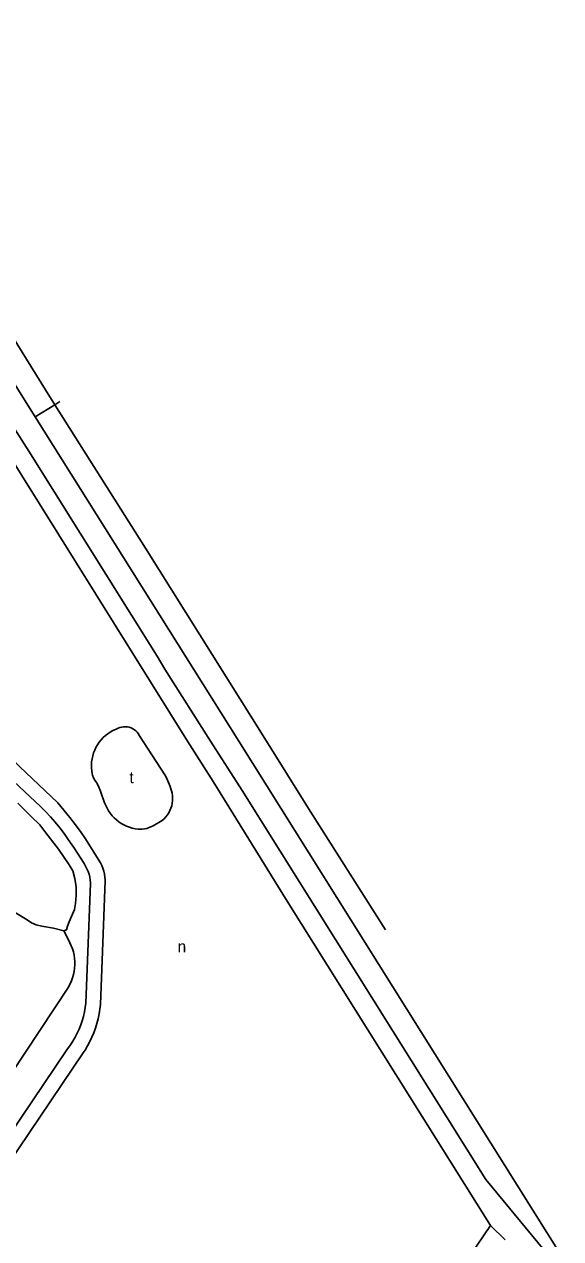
# Model space of a CAD drawing. Extents: x 158142 to 159655, y 385262 to 387204.
# Drawn here: x 159402.4 to 159588.7, y 385994 to 386415.6 of the extents above; entities that cross this region are included whole.
import ezdxf

# ---------------------------------------------------------------- set-up
doc = ezdxf.new("R2010")
doc.units = 0
for name, color, linetype in [('BLT_Basislijn', 7, 'Continuous'), ('BLT_Centroide', 7, 'Continuous'), ('BLT_Vlakafsluiter', 7, 'Continuous')]:
    doc.layers.add(name, color=color, linetype=linetype)

msp = doc.modelspace()

# ---------------------------------------------------------------- linework, layer by layer
at = {"layer": 'BLT_Basislijn'}
for p, q in [((159442.44, 386168.49), (159451.21, 386155.01)), ((159428.98, 386149.01), (159430.32, 386145.33)), ((159447.2, 386137.31), (159450.31, 386139.2)), ((159423.44, 386133.18), (159428.85, 386124.47)), ((159423.18, 386124.18), (159419.61, 386129.73)), ((159425.42, 386117.26), (159423.8, 386075.76)), ((159430.53, 386118.18), (159428.87, 386075.33)), ((159417.74, 386081.26), (159363.43, 385999.19)), ((159422.86, 386058.44), (159383.2, 386000)), ((159417.4, 386059.84), (159383.77, 386009.99)), ((159569.35, 385993.56), (159564.29, 385998.58))]:
    msp.add_line(p, q, dxfattribs=at)
for points in [[(159478.02, 386149.53), (159467.1, 386166.67), (159451.19, 386191.65), (159448.58, 386196.2), (159403.98, 386267.32), (159376.84, 386309.95), (159320.35, 386401.06), (159194.99, 386601.74), (159190.31, 386604.18), (159180.82, 386620.38), (159176.63, 386631.64), (159172.66, 386639.08), (159146.46, 386681.4), (159151.12, 386684.55)], [(159413.02, 386283.52), (159409.77, 386288.65), (159364.7, 386361.34), (159326.64, 386421.78), (159323.99, 386426.39), (159205.26, 386616.42)], [(159406.2, 386279.27), (159382.73, 386316.66), (159365.07, 386339.65), (159364.85, 386340.38), (159339.3, 386382.12), (159329.59, 386402.01), (159197.96, 386612.2)], [(159375.73, 386300.12), (159459.1, 386166.67), (159467.97, 386152.7), (159493.65, 386111.16), (159564.29, 385998.58)], [(159527.89, 386101.24), (159501.12, 386143.35), (159486.54, 386166.67), (159444.56, 386233.75), (159413.02, 386283.52)], [(159588.66, 385988.41), (159476.89, 386166.67), (159406.2, 386279.27)], [(159435, 386171.16), (159434.05, 386170.8), (159433.13, 386170.37), (159432.25, 386169.86), (159431.41, 386169.29), (159430.59, 386168.63)], [(159435, 386171.16), (159435.61, 386171.42), (159436.25, 386171.6), (159436.9, 386171.7), (159437.57, 386171.72), (159438.23, 386171.66), (159438.88, 386171.53), (159439.51, 386171.31), (159440.1, 386171.03), (159440.66, 386170.67), (159441.17, 386170.25), (159441.63, 386169.77), (159442.03, 386169.24), (159442.36, 386168.66), (159442.44, 386168.49)], [(159416.11, 386100.81), (159412.56, 386101.79), (159408.57, 386102.44), (159406.6, 386102.92), (159404.9, 386103.62), (159403.46, 386104.7), (159399.06, 386107.3), (159391.98, 386112.43), (159387.43, 386115.36), (159380.2, 386119.83), (159373.69, 386124.24), (159364.83, 386130.24), (159352.95, 386138.24), (159352.82, 386138.61), (159352.79, 386139.15), (159356.55, 386144.3), (159361.74, 386151.63), (159369, 386163.07), (159369.29, 386163.75), (159369.53, 386164.53), (159369.42, 386165.46), (159369.3, 386166.34), (159370.21, 386167.56), (159371.61, 386168.13)], [(159391.04, 386167.32), (159400.79, 386157.88), (159414.04, 386145.26)], [(159430.59, 386168.63), (159429.82, 386167.92), (159429.1, 386167.15), (159428.45, 386166.33), (159427.86, 386165.46), (159427.33, 386164.55), (159426.88, 386163.6), (159426.5, 386162.61), (159426.2, 386161.61), (159425.97, 386160.58), (159425.82, 386159.54), (159425.76, 386158.49), (159425.77, 386157.44), (159425.86, 386156.39), (159426.03, 386155.35), (159426.14, 386154.86)], [(159408.02, 386143.99), (159395.1, 386156.13), (159388.48, 386162.44)], [(159426.14, 386154.86), (159426.51, 386153.99), (159426.96, 386153.16), (159427.47, 386152.37), (159427.73, 386152.02)], [(159451.21, 386155.01), (159451.89, 386153.68), (159452.5, 386152.32), (159453.03, 386150.93), (159453.3, 386150.1)], [(159427.73, 386152.02), (159428.33, 386150.72), (159428.85, 386149.38), (159428.98, 386149.01)], [(159450.31, 386139.2), (159450.97, 386139.78), (159451.57, 386140.42), (159452.12, 386141.1), (159452.59, 386141.84), (159453, 386142.61), (159453.34, 386143.42), (159453.6, 386144.26), (159453.79, 386145.12), (159453.89, 386145.99), (159453.92, 386146.87), (159453.86, 386147.74), (159453.73, 386148.61), (159453.52, 386149.46), (159453.3, 386150.1)], [(159478.02, 386149.53), (159562.65, 386014.57), (159584.59, 385988.03), (159588.66, 385988.41)], [(159400.23, 386145.16), (159404.79, 386140.58), (159407.83, 386137.69), (159409.95, 386134.84), (159414.26, 386129.2), (159418.02, 386123.76), (159419.23, 386121.71), (159419.98, 386118.99), (159420.41, 386116.07), (159420.48, 386113.17), (159420.19, 386110.32), (159419.82, 386108.21), (159418, 386104.03), (159417.43, 386102.49), (159417.11, 386101.17), (159416.11, 386100.81)], [(159408.02, 386143.99), (159409.79, 386142.23), (159411.49, 386140.41), (159413.14, 386138.53), (159414.72, 386136.61), (159416.24, 386134.63), (159417.7, 386132.61), (159419.1, 386130.54), (159419.61, 386129.73)], [(159414.04, 386145.26), (159416.17, 386142.77), (159418.23, 386140.23), (159420.23, 386137.63), (159422.17, 386134.99), (159423.44, 386133.18)], [(159430.32, 386145.33), (159430.7, 386144.36), (159431.15, 386143.42), (159431.67, 386142.51), (159432.26, 386141.65), (159432.91, 386140.83), (159433.63, 386140.07), (159434.4, 386139.36), (159435.22, 386138.72), (159436.09, 386138.14), (159437, 386137.62), (159437.95, 386137.18), (159438.93, 386136.82), (159439.93, 386136.52), (159440.96, 386136.31), (159441.99, 386136.17), (159442.44, 386136.14)], [(159442.44, 386136.14), (159443.3, 386136.16), (159444.16, 386136.26), (159445.01, 386136.43), (159445.83, 386136.69), (159446.63, 386137.02), (159447.2, 386137.31)], [(159423.18, 386124.18), (159423.72, 386123.31), (159424.19, 386122.41), (159424.59, 386121.47), (159424.91, 386120.5), (159425.15, 386119.51), (159425.32, 386118.5), (159425.41, 386117.48), (159425.42, 386117.26)], [(159428.85, 386124.47), (159429.32, 386123.53), (159429.71, 386122.56), (159430.03, 386121.56), (159430.27, 386120.54), (159430.44, 386119.51), (159430.52, 386118.47), (159430.53, 386118.18)], [(159416.11, 386100.81), (159417.74, 386097.72), (159418.28, 386096.72), (159418.75, 386095.68), (159419.15, 386094.61), (159419.47, 386093.52), (159419.72, 386092.41), (159419.88, 386091.29), (159419.97, 386090.15), (159419.98, 386089.01), (159419.9, 386087.88), (159419.75, 386086.75), (159419.52, 386085.63), (159419.21, 386084.54), (159418.82, 386083.47), (159418.36, 386082.43), (159417.83, 386081.42), (159417.74, 386081.26)], [(159423.8, 386075.76), (159423.61, 386074.21), (159423.34, 386072.67), (159422.99, 386071.15), (159422.57, 386069.65), (159422.07, 386068.17), (159421.49, 386066.72), (159420.84, 386065.3), (159420.12, 386063.91), (159419.33, 386062.57), (159418.46, 386061.27), (159417.54, 386060.01), (159417.4, 386059.84)], [(159428.87, 386075.33), (159428.68, 386073.65), (159428.41, 386071.98), (159428.07, 386070.33), (159427.64, 386068.69), (159427.14, 386067.08), (159426.57, 386065.49), (159425.92, 386063.94), (159425.19, 386062.41), (159424.4, 386060.92), (159423.54, 386059.47), (159422.86, 386058.44)], [(159564.29, 385998.58), (159537.79, 385959.39), (159521.82, 385934.86)]]:
    msp.add_lwpolyline(points, dxfattribs=at)
at = {"layer": 'BLT_Vlakafsluiter'}
for p, q in [((159406.2, 386279.27), (159413.02, 386283.52)), ((159413.02, 386283.52), (159414.81, 386284.64))]:
    msp.add_line(p, q, dxfattribs=at)

# ---------------------------------------------------------------- texts
at = {"layer": 'BLT_Centroide'}
for s, p in [('t', (159438.93, 386152.1)), ('n', (159455.66, 386093.4))]:
    msp.add_text(s, height=4, dxfattribs=at).set_placement(p)

doc.saveas('drawing.dxf')
